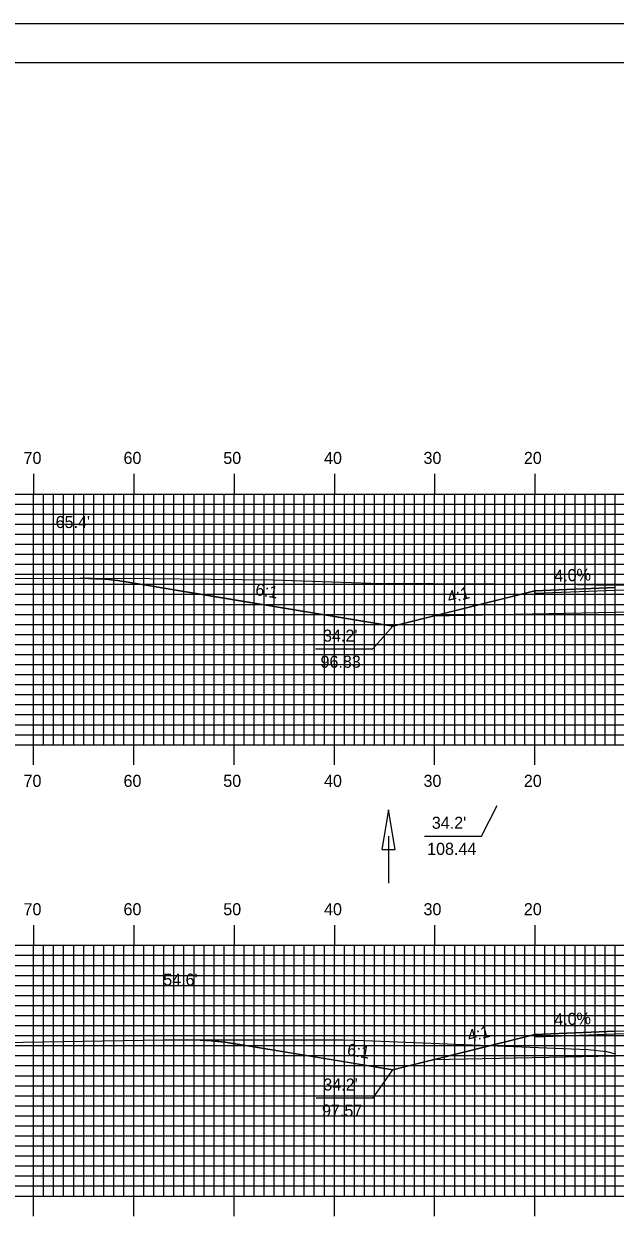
# Model space of a CAD drawing. Extents: x 1774777 to 1775120, y 442591 to 442811.
# Drawn here: x 1774871.7 to 1774930.7, y 442691.2 to 442810.5 of the extents above; entities that cross this region are included whole.
import ezdxf

# ---------------------------------------------------------------- set-up
doc = ezdxf.new("R2010")
doc.units = 0
for name, color, linetype in [('ANNOTATION', 7, 'Continuous'), ('BORDER', 7, 'Continuous'), ('D_Drainage_Ditch_Line', 7, 'Continuous'), ('D_Roadway_Centerline', 7, 'Continuous'), ('D_Roadway_Edge_Shoulder', 7, 'Continuous'), ('D_Roadway_SlopeLines', 7, 'Continuous'), ('D_Roadway_SubGrade', 7, 'Continuous'), ('D_Text_Standard', 7, 'Continuous'), ('H_V ANNOTATION', 7, 'Continuous'), ('MAJOR', 7, 'Continuous'), ('MINOR', 7, 'Continuous'), ('PLOT BOUNDARY', 7, 'Continuous'), ('S_Roadway_Centerline', 7, 'Continuous')]:
    doc.layers.add(name, color=color, linetype=linetype)

msp = doc.modelspace()

# ---------------------------------------------------------------- linework, layer by layer
at = {"layer": 'ANNOTATION'}
for points in [[(1774900.82, 442748.22), (1774906.52, 442748.22), (1774908.51, 442750.49)], [(1774911.67, 442729.56), (1774917.36, 442729.56), (1774918.93, 442732.62)], [(1774900.86, 442703.46), (1774906.55, 442703.46), (1774908.51, 442706.24)]]:
    msp.add_lwpolyline(points, dxfattribs=at)
at = {"layer": 'BORDER'}
msp.add_lwpolyline([(1774793.09, 442596.67), (1775113.09, 442596.67), (1775113.09, 442806.67), (1774793.09, 442806.67)], close=True, dxfattribs=at)
at = {"layer": 'D_Drainage_Ditch_Line'}
msp.add_line((1774908.1, 442729.55), (1774908.1, 442724.85), dxfattribs=at)
msp.add_lwpolyline([(1774907.44, 442728.24), (1774908.75, 442728.24), (1774908.1, 442732.17)], close=True, dxfattribs=at)
at = {"layer": 'D_Roadway_Centerline'}
for points in [[(1774877.33, 442755.27), (1774878.18, 442755.25), (1774878.58, 442755.24), (1774878.85, 442755.23), (1774879.83, 442755.17), (1774881.08, 442755.04), (1774881.28, 442755.01), (1774882.33, 442754.85), (1774882.33, 442754.85), (1774891.67, 442753.3), (1774908.51, 442750.49), (1774908.51, 442750.49), (1774910.13, 442750.89), (1774912.51, 442751.49), (1774921.05, 442753.63), (1774922.69, 442754.03), (1774930.69, 442754.35)], [(1774888.04, 442709.23), (1774889.29, 442709.21), (1774890.43, 442709.14), (1774890.54, 442709.13), (1774890.71, 442709.11), (1774891.79, 442709), (1774892.52, 442708.89), (1774893.04, 442708.82), (1774903.36, 442707.1), (1774908.51, 442706.24), (1774909.43, 442706.47), (1774912.51, 442707.24), (1774916.84, 442708.32), (1774922.69, 442709.78), (1774930.69, 442710.1), (1774941.71, 442710.32), (1774942.69, 442710.34), (1774944, 442710.32), (1774954.68, 442710.1), (1774962.69, 442709.78), (1774972.86, 442707.24), (1774975.44, 442706.6), (1774980.56, 442705.32)]]:
    msp.add_lwpolyline(points, dxfattribs=at)
at = {"layer": 'D_Roadway_Edge_Shoulder'}
for points in [[(1774930.69, 442754.35), (1774922.69, 442754.03), (1774922.69, 442753.78), (1774930.69, 442754.1)], [(1774930.69, 442710.1), (1774922.69, 442709.78), (1774922.69, 442709.53), (1774930.69, 442709.85)]]:
    msp.add_lwpolyline(points, close=True, dxfattribs=at)
at = {"layer": 'D_Roadway_SlopeLines'}
for points in [[(1774908.51, 442750.49), (1774882.33, 442754.85), (1774881.08, 442755.04), (1774879.83, 442755.17), (1774878.58, 442755.24), (1774877.33, 442755.27)], [(1774922.69, 442754.03), (1774908.51, 442750.49)], [(1774922.69, 442709.78), (1774908.51, 442706.24)], [(1774908.51, 442706.24), (1774893.04, 442708.82), (1774891.79, 442709), (1774890.54, 442709.13), (1774889.29, 442709.21), (1774888.04, 442709.23)]]:
    msp.add_lwpolyline(points, dxfattribs=at)
at = {"layer": 'D_Roadway_SubGrade'}
for points in [[(1774930.69, 442751.85), (1774912.51, 442751.49), (1774922.69, 442754.03), (1774922.69, 442753.78), (1774930.69, 442754.1), (1774942.68, 442754.34), (1774954.68, 442754.1), (1774962.69, 442753.78), (1774962.69, 442754.03), (1774972.86, 442751.49), (1774954.68, 442751.85), (1774942.68, 442752.09)], [(1774930.69, 442707.6), (1774912.51, 442707.24), (1774922.69, 442709.78), (1774922.69, 442709.53), (1774930.69, 442709.85), (1774942.69, 442710.09), (1774954.68, 442709.85), (1774962.69, 442709.53), (1774962.69, 442709.78), (1774972.86, 442707.24), (1774954.68, 442707.6), (1774942.69, 442707.84)]]:
    msp.add_lwpolyline(points, close=True, dxfattribs=at)
at = {"layer": 'MAJOR'}
for p, q in [((1774872.69, 442765.67), (1774872.69, 442763.67)), ((1774882.69, 442765.67), (1774882.69, 442763.67)), ((1774892.69, 442765.67), (1774892.69, 442763.67)), ((1774902.69, 442765.67), (1774902.69, 442763.67)), ((1774912.69, 442765.67), (1774912.69, 442763.67)), ((1774922.69, 442765.67), (1774922.69, 442763.67)), ((1774802.69, 442763.67), (1775082.69, 442763.67)), ((1774802.69, 442763.67), (1775082.69, 442763.67)), ((1774872.69, 442738.67), (1774872.69, 442763.67)), ((1774882.69, 442738.67), (1774882.69, 442763.67)), ((1774892.69, 442738.67), (1774892.69, 442763.67)), ((1774902.69, 442738.67), (1774902.69, 442763.67)), ((1774912.69, 442738.67), (1774912.69, 442763.67)), ((1774922.69, 442738.67), (1774922.69, 442763.67)), ((1774802.69, 442758.67), (1775082.69, 442758.67)), ((1774802.69, 442753.67), (1775082.69, 442753.67)), ((1774802.69, 442748.67), (1775082.69, 442748.67)), ((1774802.69, 442743.67), (1775082.69, 442743.67)), ((1774802.69, 442738.67), (1775082.69, 442738.67)), ((1774802.69, 442738.67), (1775082.69, 442738.67)), ((1774872.69, 442736.66), (1774872.69, 442738.67)), ((1774882.69, 442736.66), (1774882.69, 442738.67)), ((1774892.69, 442736.66), (1774892.69, 442738.67)), ((1774902.69, 442736.66), (1774902.69, 442738.67)), ((1774912.69, 442736.66), (1774912.69, 442738.67)), ((1774922.69, 442736.66), (1774922.69, 442738.67)), ((1774872.69, 442720.67), (1774872.69, 442718.67)), ((1774882.69, 442720.67), (1774882.69, 442718.67)), ((1774892.69, 442720.67), (1774892.69, 442718.67)), ((1774902.69, 442720.67), (1774902.69, 442718.67)), ((1774912.69, 442720.67), (1774912.69, 442718.67)), ((1774922.69, 442720.67), (1774922.69, 442718.67)), ((1774802.69, 442718.67), (1775082.69, 442718.67)), ((1774802.69, 442718.67), (1775082.69, 442718.67)), ((1774872.69, 442693.67), (1774872.69, 442718.67)), ((1774882.69, 442693.67), (1774882.69, 442718.67)), ((1774892.69, 442693.67), (1774892.69, 442718.67)), ((1774902.69, 442693.67), (1774902.69, 442718.67)), ((1774912.69, 442693.67), (1774912.69, 442718.67)), ((1774922.69, 442693.67), (1774922.69, 442718.67)), ((1774802.69, 442713.67), (1775082.69, 442713.67)), ((1774802.69, 442708.67), (1775082.69, 442708.67)), ((1774802.69, 442703.67), (1775082.69, 442703.67)), ((1774802.69, 442698.67), (1775082.69, 442698.67)), ((1774802.69, 442693.67), (1775082.69, 442693.67)), ((1774802.69, 442693.67), (1775082.69, 442693.67)), ((1774872.69, 442691.66), (1774872.69, 442693.67)), ((1774882.69, 442691.66), (1774882.69, 442693.67)), ((1774892.69, 442691.66), (1774892.69, 442693.67)), ((1774902.69, 442691.66), (1774902.69, 442693.67)), ((1774912.69, 442691.66), (1774912.69, 442693.67)), ((1774922.69, 442691.66), (1774922.69, 442693.67))]:
    msp.add_line(p, q, dxfattribs=at)
at = {"layer": 'MINOR'}
for p, q in [((1774873.69, 442738.67), (1774873.69, 442763.67)), ((1774874.69, 442738.67), (1774874.69, 442763.67)), ((1774875.69, 442738.67), (1774875.69, 442763.67)), ((1774876.69, 442738.67), (1774876.69, 442763.67)), ((1774877.69, 442738.67), (1774877.69, 442763.67)), ((1774878.69, 442738.67), (1774878.69, 442763.67)), ((1774879.69, 442738.67), (1774879.69, 442763.67)), ((1774880.69, 442738.67), (1774880.69, 442763.67)), ((1774881.69, 442738.67), (1774881.69, 442763.67)), ((1774883.69, 442738.67), (1774883.69, 442763.67)), ((1774884.69, 442738.67), (1774884.69, 442763.67)), ((1774885.69, 442738.67), (1774885.69, 442763.67)), ((1774886.69, 442738.67), (1774886.69, 442763.67)), ((1774887.69, 442738.67), (1774887.69, 442763.67)), ((1774888.69, 442738.67), (1774888.69, 442763.67)), ((1774889.69, 442738.67), (1774889.69, 442763.67)), ((1774890.69, 442738.67), (1774890.69, 442763.67)), ((1774891.69, 442738.67), (1774891.69, 442763.67)), ((1774893.69, 442738.67), (1774893.69, 442763.67)), ((1774894.69, 442738.67), (1774894.69, 442763.67)), ((1774895.69, 442738.67), (1774895.69, 442763.67)), ((1774896.69, 442738.67), (1774896.69, 442763.67)), ((1774897.69, 442738.67), (1774897.69, 442763.67)), ((1774898.69, 442738.67), (1774898.69, 442763.67)), ((1774899.69, 442738.67), (1774899.69, 442763.67)), ((1774900.69, 442738.67), (1774900.69, 442763.67)), ((1774901.69, 442738.67), (1774901.69, 442763.67)), ((1774903.69, 442738.67), (1774903.69, 442763.67)), ((1774904.69, 442738.67), (1774904.69, 442763.67)), ((1774905.69, 442738.67), (1774905.69, 442763.67)), ((1774906.69, 442738.67), (1774906.69, 442763.67)), ((1774907.69, 442738.67), (1774907.69, 442763.67)), ((1774908.69, 442738.67), (1774908.69, 442763.67)), ((1774909.69, 442738.67), (1774909.69, 442763.67)), ((1774910.69, 442738.67), (1774910.69, 442763.67)), ((1774911.69, 442738.67), (1774911.69, 442763.67)), ((1774913.69, 442738.67), (1774913.69, 442763.67)), ((1774914.69, 442738.67), (1774914.69, 442763.67)), ((1774915.69, 442738.67), (1774915.69, 442763.67)), ((1774916.69, 442738.67), (1774916.69, 442763.67)), ((1774917.69, 442738.67), (1774917.69, 442763.67)), ((1774918.69, 442738.67), (1774918.69, 442763.67)), ((1774919.69, 442738.67), (1774919.69, 442763.67)), ((1774920.69, 442738.67), (1774920.69, 442763.67)), ((1774921.69, 442738.67), (1774921.69, 442763.67)), ((1774923.69, 442738.67), (1774923.69, 442763.67)), ((1774924.69, 442738.67), (1774924.69, 442763.67)), ((1774925.69, 442738.67), (1774925.69, 442763.67)), ((1774926.69, 442738.67), (1774926.69, 442763.67)), ((1774927.69, 442738.67), (1774927.69, 442763.67)), ((1774928.69, 442738.67), (1774928.69, 442763.67)), ((1774929.69, 442738.67), (1774929.69, 442763.67)), ((1774930.69, 442738.67), (1774930.69, 442763.67)), ((1774802.69, 442762.67), (1775082.69, 442762.67)), ((1774802.69, 442761.67), (1775082.69, 442761.67)), ((1774802.69, 442760.67), (1775082.69, 442760.67)), ((1774802.69, 442759.67), (1775082.69, 442759.67)), ((1774802.69, 442757.67), (1775082.69, 442757.67)), ((1774802.69, 442756.67), (1775082.69, 442756.67)), ((1774802.69, 442755.67), (1775082.69, 442755.67)), ((1774802.69, 442754.67), (1775082.69, 442754.67)), ((1774802.69, 442752.67), (1775082.69, 442752.67)), ((1774802.69, 442751.67), (1775082.69, 442751.67)), ((1774802.69, 442750.67), (1775082.69, 442750.67)), ((1774802.69, 442749.67), (1775082.69, 442749.67)), ((1774802.69, 442747.67), (1775082.69, 442747.67)), ((1774802.69, 442746.67), (1775082.69, 442746.67)), ((1774802.69, 442745.67), (1775082.69, 442745.67)), ((1774802.69, 442744.67), (1775082.69, 442744.67)), ((1774802.69, 442742.67), (1775082.69, 442742.67)), ((1774802.69, 442741.67), (1775082.69, 442741.67)), ((1774802.69, 442740.67), (1775082.69, 442740.67)), ((1774802.69, 442739.67), (1775082.69, 442739.67)), ((1774873.69, 442693.67), (1774873.69, 442718.67)), ((1774874.69, 442693.67), (1774874.69, 442718.67)), ((1774875.69, 442693.67), (1774875.69, 442718.67)), ((1774876.69, 442693.67), (1774876.69, 442718.67)), ((1774877.69, 442693.67), (1774877.69, 442718.67)), ((1774878.69, 442693.67), (1774878.69, 442718.67)), ((1774879.69, 442693.67), (1774879.69, 442718.67)), ((1774880.69, 442693.67), (1774880.69, 442718.67)), ((1774881.69, 442693.67), (1774881.69, 442718.67)), ((1774883.69, 442693.67), (1774883.69, 442718.67)), ((1774884.69, 442693.67), (1774884.69, 442718.67)), ((1774885.69, 442693.67), (1774885.69, 442718.67)), ((1774886.69, 442693.67), (1774886.69, 442718.67)), ((1774887.69, 442693.67), (1774887.69, 442718.67)), ((1774888.69, 442693.67), (1774888.69, 442718.67)), ((1774889.69, 442693.67), (1774889.69, 442718.67)), ((1774890.69, 442693.67), (1774890.69, 442718.67)), ((1774891.69, 442693.67), (1774891.69, 442718.67)), ((1774893.69, 442693.67), (1774893.69, 442718.67)), ((1774894.69, 442693.67), (1774894.69, 442718.67)), ((1774895.69, 442693.67), (1774895.69, 442718.67)), ((1774896.69, 442693.67), (1774896.69, 442718.67)), ((1774897.69, 442693.67), (1774897.69, 442718.67)), ((1774898.69, 442693.67), (1774898.69, 442718.67)), ((1774899.69, 442693.67), (1774899.69, 442718.67)), ((1774900.69, 442693.67), (1774900.69, 442718.67)), ((1774901.69, 442693.67), (1774901.69, 442718.67)), ((1774903.69, 442693.67), (1774903.69, 442718.67)), ((1774904.69, 442693.67), (1774904.69, 442718.67)), ((1774905.69, 442693.67), (1774905.69, 442718.67)), ((1774906.69, 442693.67), (1774906.69, 442718.67)), ((1774907.69, 442693.67), (1774907.69, 442718.67)), ((1774908.69, 442693.67), (1774908.69, 442718.67)), ((1774909.69, 442693.67), (1774909.69, 442718.67)), ((1774910.69, 442693.67), (1774910.69, 442718.67)), ((1774911.69, 442693.67), (1774911.69, 442718.67)), ((1774913.69, 442693.67), (1774913.69, 442718.67)), ((1774914.69, 442693.67), (1774914.69, 442718.67)), ((1774915.69, 442693.67), (1774915.69, 442718.67)), ((1774916.69, 442693.67), (1774916.69, 442718.67)), ((1774917.69, 442693.67), (1774917.69, 442718.67)), ((1774918.69, 442693.67), (1774918.69, 442718.67)), ((1774919.69, 442693.67), (1774919.69, 442718.67)), ((1774920.69, 442693.67), (1774920.69, 442718.67)), ((1774921.69, 442693.67), (1774921.69, 442718.67)), ((1774923.69, 442693.67), (1774923.69, 442718.67)), ((1774924.69, 442693.67), (1774924.69, 442718.67)), ((1774925.69, 442693.67), (1774925.69, 442718.67)), ((1774926.69, 442693.67), (1774926.69, 442718.67)), ((1774927.69, 442693.67), (1774927.69, 442718.67)), ((1774928.69, 442693.67), (1774928.69, 442718.67)), ((1774929.69, 442693.67), (1774929.69, 442718.67)), ((1774930.69, 442693.67), (1774930.69, 442718.67)), ((1774802.69, 442717.67), (1775082.69, 442717.67)), ((1774802.69, 442716.67), (1775082.69, 442716.67)), ((1774802.69, 442715.67), (1775082.69, 442715.67)), ((1774802.69, 442714.67), (1775082.69, 442714.67)), ((1774802.69, 442712.67), (1775082.69, 442712.67)), ((1774802.69, 442711.67), (1775082.69, 442711.67)), ((1774802.69, 442710.67), (1775082.69, 442710.67)), ((1774802.69, 442709.67), (1775082.69, 442709.67)), ((1774802.69, 442707.67), (1775082.69, 442707.67)), ((1774802.69, 442706.67), (1775082.69, 442706.67)), ((1774802.69, 442705.67), (1775082.69, 442705.67)), ((1774802.69, 442704.67), (1775082.69, 442704.67)), ((1774802.69, 442702.67), (1775082.69, 442702.67)), ((1774802.69, 442701.67), (1775082.69, 442701.67)), ((1774802.69, 442700.67), (1775082.69, 442700.67)), ((1774802.69, 442699.67), (1775082.69, 442699.67)), ((1774802.69, 442697.67), (1775082.69, 442697.67)), ((1774802.69, 442696.67), (1775082.69, 442696.67)), ((1774802.69, 442695.67), (1775082.69, 442695.67)), ((1774802.69, 442694.67), (1775082.69, 442694.67))]:
    msp.add_line(p, q, dxfattribs=at)
at = {"layer": 'PLOT BOUNDARY'}
msp.add_lwpolyline([(1774776.9, 442590.55), (1775116.9, 442590.55), (1775116.9, 442810.55), (1774776.9, 442810.55)], close=True, dxfattribs=at)
at = {"layer": 'S_Roadway_Centerline'}
for points in [[(1774862.9, 442755.25), (1774883.51, 442755.27), (1774884.25, 442755.26), (1774896.55, 442755.12), (1774906.35, 442754.77), (1774924.96, 442754.69), (1774928.82, 442754.63), (1774931.03, 442754.6), (1774933.22, 442754.61), (1774942.16, 442754.57), (1774952.45, 442753.91), (1774953.78, 442753.87), (1774955.15, 442753.78), (1774965.57, 442753.45), (1774974.36, 442753.34), (1774979.36, 442753.3), (1774988.24, 442752.43), (1775004.08, 442751.78), (1775012.23, 442750.26)], [(1774863.7, 442708.87), (1774879.58, 442709.13), (1774885.62, 442709.23), (1774903.58, 442709.25), (1774905.7, 442709.19), (1774927.99, 442708.28), (1774929.82, 442708.07), (1774930.73, 442707.85)]]:
    msp.add_lwpolyline(points, dxfattribs=at)

# ---------------------------------------------------------------- texts
at = {"layer": 'ANNOTATION'}
for s, rotation, p in [('4.0%', 2.2905, (1774924.64, 442754.91)), ('6:1', 350.5384, (1774894.75, 442753.61)), ('4:1', 14.0387, (1774914.12, 442752.76)), ('4.0%', 2.2905, (1774924.64, 442710.66)), ('4:1', 14.0392, (1774916.13, 442709.01)), ('6:1', 350.5389, (1774903.9, 442707.72))]:
    msp.add_text(s, height=1.2, rotation=rotation, dxfattribs=at).set_placement(p)
for s, p in [("34.2'", (1774901.56, 442748.95)), ('96.83', (1774901.31, 442746.35)), ("34.2'", (1774912.41, 442730.29)), ('108.44', (1774911.94, 442727.69)), ("34.2'", (1774901.59, 442704.19)), ('97.57', (1774901.46, 442701.59))]:
    msp.add_text(s, height=1.2, dxfattribs=at).set_placement(p)
at = {"layer": 'D_Text_Standard'}
for s, p in [("65.4'", (1774874.89, 442760.28)), ("54.6'", (1774885.62, 442714.65))]:
    msp.add_text(s, height=1.2, dxfattribs=at).set_placement(p)
at = {"layer": 'H_V ANNOTATION'}
for s, p in [('70', (1774871.69, 442766.67)), ('60', (1774881.66, 442766.67)), ('50', (1774891.61, 442766.67)), ('40', (1774901.66, 442766.67)), ('30', (1774911.58, 442766.67)), ('20', (1774921.59, 442766.67)), ('70', (1774871.69, 442734.47)), ('60', (1774881.66, 442734.47)), ('50', (1774891.61, 442734.47)), ('40', (1774901.66, 442734.47)), ('30', (1774911.58, 442734.47)), ('20', (1774921.59, 442734.47)), ('70', (1774871.69, 442721.67)), ('60', (1774881.66, 442721.67)), ('50', (1774891.61, 442721.67)), ('40', (1774901.66, 442721.67)), ('30', (1774911.58, 442721.67)), ('20', (1774921.59, 442721.67))]:
    msp.add_text(s, height=1.2, dxfattribs=at).set_placement(p)

doc.saveas('drawing.dxf')
